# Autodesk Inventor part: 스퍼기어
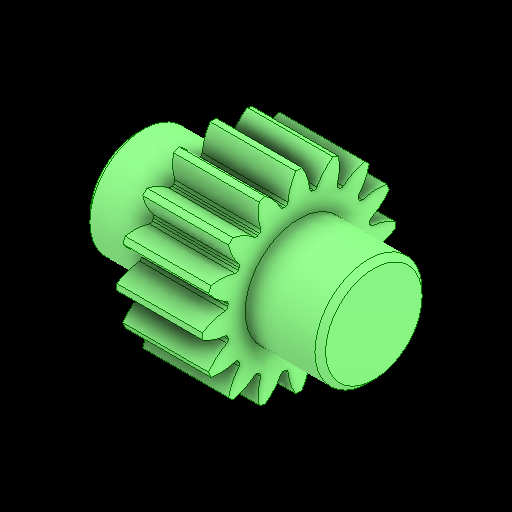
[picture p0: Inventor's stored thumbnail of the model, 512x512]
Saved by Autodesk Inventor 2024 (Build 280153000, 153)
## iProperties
Created: 2025-10
Part Number: 스퍼기어
Material: 강철, 합금
Document SubType Name: Modeling
Designer: EDU03
Density: 7.73 g/cm^3
Appearance: 기본값
Author: jhkim
Sending System: Autodesk Inventor 2026
Preprocessor: ST-DEVELOPER v20.1
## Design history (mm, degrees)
node "스퍼기어1"
node "솔리드2"
node "솔리드1"
